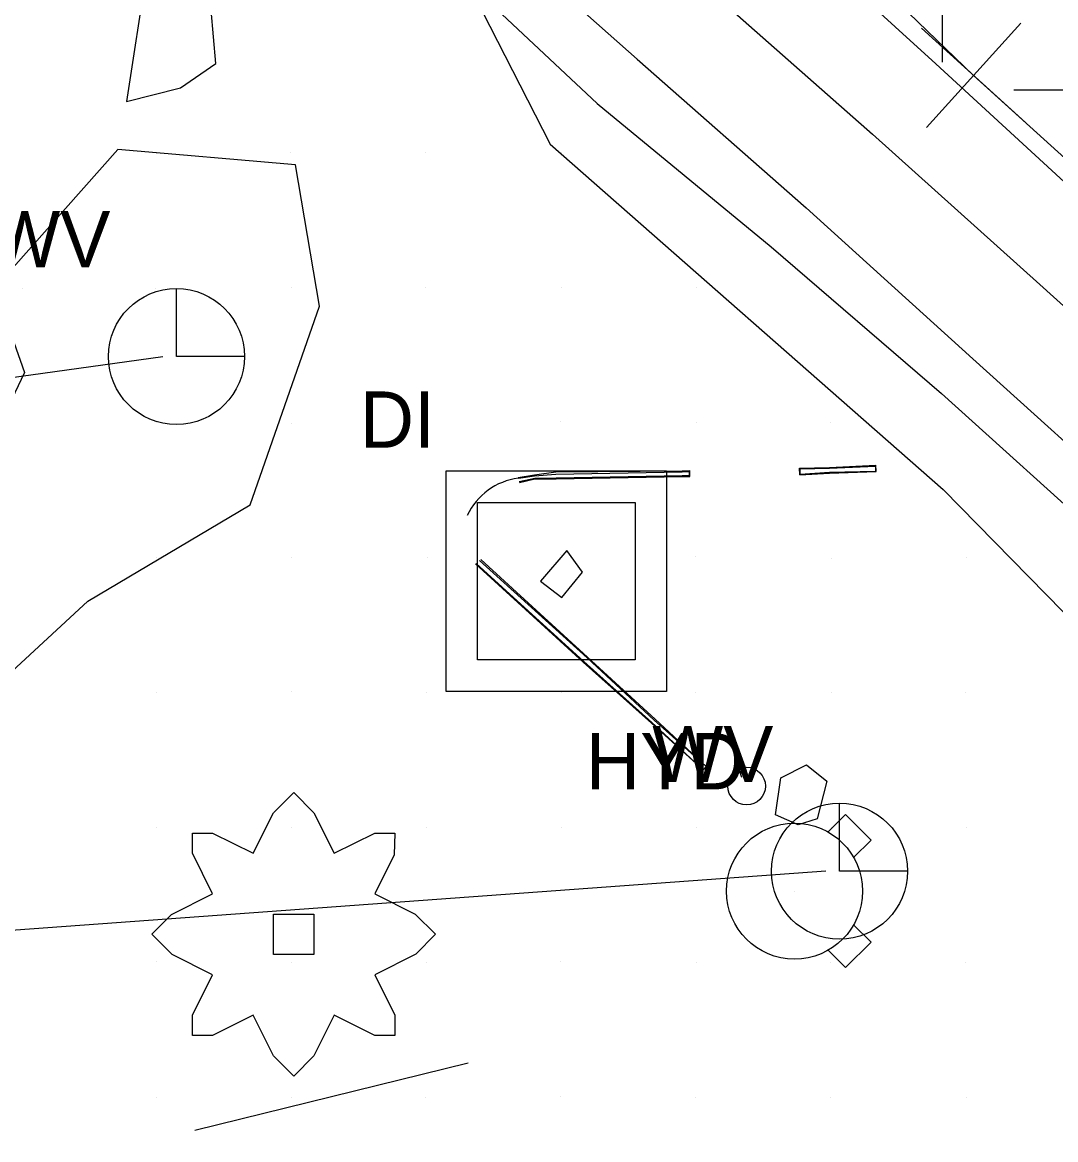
# Model space of a CAD drawing. Extents: x 1602514 to 1609837, y 863887 to 871157.
# Drawn here: x 1604998.8 to 1605113.6, y 866494.3 to 866618.4 of the extents above; entities that cross this region are included whole.
import ezdxf

# ---------------------------------------------------------------- set-up
doc = ezdxf.new("R2010")
doc.units = 0
for name, color, linetype in [('Default', 7, 'Continuous'), ('Drainage-Structures', 7, 'Continuous'), ('Environmental-New trees', 7, 'Continuous'), ('Survey-Centerline', 7, 'Continuous'), ('Survey-Drainage structures-concrete', 7, 'Continuous'), ('Survey-Edge of pavement', 7, 'Continuous'), ('Survey-Point', 7, 'Continuous'), ('Survey-Ridge Lines', 7, 'Continuous'), ('Survey-Shoulders', 7, 'Continuous'), ('Survey-Signs', 7, 'Continuous'), ('Survey-Spot dirt', 7, 'Continuous'), ('Survey-Vegetation trees', 7, 'Continuous'), ('Survey-Walls', 7, 'Continuous'), ('Text General Notes', 7, 'Continuous'), ('USER-Boulder', 7, 'Continuous'), ('USER-Manhole lid', 7, 'Continuous'), ('USER-RipRap', 7, 'Continuous'), ('Utility-Water', 7, 'Continuous')]:
    doc.layers.add(name, color=color, linetype=linetype)

msp = doc.modelspace()

# ---------------------------------------------------------------- linework, layer by layer
at = {"layer": 'Default'}
msp.add_lwpolyline([(1605152.49, 866568.76), (1605131.42, 866588.1), (1605104.45, 866612.51), (1605090, 866626.47), (1605088.69, 866628.71)], dxfattribs=at)
msp.add_lwpolyline([(1605152.49, 866568.76), (1605131.42, 866588.1), (1605104.45, 866612.51), (1605090, 866626.47), (1605088.69, 866628.71)], dxfattribs=at)
at = {"layer": 'Drainage-Structures'}
for p, q in [((1605045.84, 866568.56), (1605070.34, 866568.56)), ((1605045.84, 866544.06), (1605045.84, 866568.56)), ((1605045.84, 866568.56), (1605070.34, 866568.56)), ((1605045.84, 866544.06), (1605045.84, 866568.56)), ((1605070.34, 866568.56), (1605070.34, 866544.06)), ((1605070.34, 866568.56), (1605070.34, 866544.06)), ((1605049.34, 866565.06), (1605066.84, 866565.06)), ((1605049.34, 866547.56), (1605049.34, 866565.06)), ((1605049.34, 866565.06), (1605066.84, 866565.06)), ((1605049.34, 866547.56), (1605049.34, 866565.06)), ((1605066.84, 866565.06), (1605066.84, 866547.56)), ((1605066.84, 866565.06), (1605066.84, 866547.56)), ((1605066.84, 866547.56), (1605049.34, 866547.56)), ((1605066.84, 866547.56), (1605049.34, 866547.56)), ((1605070.34, 866544.06), (1605045.84, 866544.06)), ((1605070.34, 866544.06), (1605045.84, 866544.06))]:
    msp.add_line(p, q, dxfattribs=at)
at = {"layer": 'Environmental-New trees'}
for points in [[(1605017.65, 866505.83), (1605017.65, 866508.08), (1605019.9, 866512.58), (1605015.4, 866514.83), (1605013.15, 866517.08), (1605015.34, 866519.28), (1605019.9, 866521.58), (1605017.65, 866526.08), (1605017.65, 866528.33), (1605019.9, 866528.33), (1605024.4, 866526.08), (1605026.65, 866530.59), (1605028.91, 866532.84), (1605031.16, 866530.59), (1605033.41, 866526.08), (1605037.91, 866528.33), (1605040.16, 866528.33), (1605040.07, 866525.91), (1605037.91, 866521.58), (1605042.41, 866519.33), (1605044.66, 866517.08), (1605042.47, 866514.89), (1605037.91, 866512.58), (1605040.16, 866508.08), (1605040.16, 866505.83), (1605037.91, 866505.83), (1605033.41, 866508.08), (1605031.16, 866503.58), (1605028.91, 866501.33), (1605026.65, 866503.58), (1605024.4, 866508.08), (1605019.9, 866505.83)], [(1605017.65, 866505.83), (1605017.65, 866508.08), (1605019.9, 866512.58), (1605015.4, 866514.83), (1605013.15, 866517.08), (1605015.34, 866519.28), (1605019.9, 866521.58), (1605017.65, 866526.08), (1605017.65, 866528.33), (1605019.9, 866528.33), (1605024.4, 866526.08), (1605026.65, 866530.59), (1605028.91, 866532.84), (1605031.16, 866530.59), (1605033.41, 866526.08), (1605037.91, 866528.33), (1605040.16, 866528.33), (1605040.07, 866525.91), (1605037.91, 866521.58), (1605042.41, 866519.33), (1605044.66, 866517.08), (1605042.47, 866514.89), (1605037.91, 866512.58), (1605040.16, 866508.08), (1605040.16, 866505.83), (1605037.91, 866505.83), (1605033.41, 866508.08), (1605031.16, 866503.58), (1605028.91, 866501.33), (1605026.65, 866503.58), (1605024.4, 866508.08), (1605019.9, 866505.83)], [(1605026.65, 866519.33), (1605031.16, 866519.33), (1605031.16, 866514.83), (1605026.65, 866514.83)], [(1605026.65, 866519.33), (1605031.16, 866519.33), (1605031.16, 866514.83), (1605026.65, 866514.83)]]:
    msp.add_lwpolyline(points, close=True, dxfattribs=at)
at = {"layer": 'Survey-Centerline'}
msp.add_lwpolyline([(1605037.69, 866656.39), (1605055.94, 866639.3), (1605074.48, 866622.54), (1605093.22, 866605.99), (1605111.81, 866589.27), (1605130.38, 866572.54), (1605149.03, 866555.9), (1605167.54, 866539.1), (1605186.09, 866522.35), (1605204.45, 866505.38), (1605222.87, 866488.48), (1605241.24, 866471.52), (1605259.83, 866454.8), (1605278.24, 866437.88), (1605296.47, 866420.77), (1605314.1, 866402.9), (1605330.94, 866384.38), (1605346.83, 866365.09), (1605361.55, 866344.83), (1605375.5, 866323.96)], dxfattribs=at)
msp.add_lwpolyline([(1605037.69, 866656.39), (1605055.94, 866639.3), (1605074.48, 866622.54), (1605093.22, 866605.99), (1605111.81, 866589.27), (1605130.38, 866572.54), (1605149.03, 866555.9), (1605167.54, 866539.1), (1605186.09, 866522.35), (1605204.45, 866505.38), (1605222.87, 866488.48), (1605241.24, 866471.52), (1605259.83, 866454.8), (1605278.24, 866437.88), (1605296.47, 866420.77), (1605314.1, 866402.9), (1605330.94, 866384.38), (1605346.83, 866365.09), (1605361.55, 866344.83), (1605375.5, 866323.96)], dxfattribs=at)
at = {"layer": 'Survey-Drainage structures-concrete'}
msp.add_lwpolyline([(1605056.34, 866556.31), (1605058.69, 866554.51), (1605061.01, 866557.32), (1605059.24, 866559.71)], close=True, dxfattribs=at)
msp.add_lwpolyline([(1605056.34, 866556.31), (1605058.69, 866554.51), (1605061.01, 866557.32), (1605059.24, 866559.71)], close=True, dxfattribs=at)
at = {"layer": 'Survey-Edge of pavement'}
for points in [[(1605045, 866665.21), (1605063.24, 866647.41), (1605081.79, 866630.65), (1605100.27, 866613.81), (1605118.67, 866596.89), (1605137.24, 866580.16), (1605155.84, 866563.45), (1605174.61, 866546.94), (1605193.13, 866529.98), (1605211.59, 866513.11), (1605230.01, 866496.21), (1605248.38, 866479.26), (1605267.08, 866462.66), (1605285.49, 866445.74), (1605303.72, 866428.63), (1605322.49, 866409.74), (1605339.33, 866391.21), (1605355.22, 866371.92), (1605369.93, 866351.67), (1605383.89, 866330.79)], [(1605045, 866665.21), (1605063.24, 866647.41), (1605081.79, 866630.65), (1605100.27, 866613.81), (1605118.67, 866596.89), (1605137.24, 866580.16), (1605155.84, 866563.45), (1605174.61, 866546.94), (1605193.13, 866529.98), (1605211.59, 866513.11), (1605230.01, 866496.21), (1605248.38, 866479.26), (1605267.08, 866462.66), (1605285.49, 866445.74), (1605303.72, 866428.63), (1605322.49, 866409.74), (1605339.33, 866391.21), (1605355.22, 866371.92), (1605369.93, 866351.67), (1605383.89, 866330.79)], [(1605024.15, 866652.85), (1605048.37, 866630.9), (1605067.06, 866614.3), (1605085.84, 866597.8), (1605104.37, 866581.02), (1605122.94, 866564.29), (1605141.59, 866547.64), (1605160.11, 866530.85), (1605178.38, 866513.98), (1605196.73, 866497.01), (1605215.15, 866480.11), (1605233.53, 866463.16), (1605252.21, 866446.54), (1605270.61, 866429.62), (1605288.84, 866412.51), (1605305.39, 866395.8), (1605322.22, 866377.27), (1605338.18, 866358.03), (1605352.89, 866337.77)], [(1605024.15, 866652.85), (1605048.37, 866630.9), (1605067.06, 866614.3), (1605085.84, 866597.8), (1605104.37, 866581.02), (1605122.94, 866564.29), (1605141.59, 866547.64), (1605160.11, 866530.85), (1605178.38, 866513.98), (1605196.73, 866497.01), (1605215.15, 866480.11), (1605233.53, 866463.16), (1605252.21, 866446.54), (1605270.61, 866429.62), (1605288.84, 866412.51), (1605305.39, 866395.8), (1605322.22, 866377.27), (1605338.18, 866358.03), (1605352.89, 866337.77)]]:
    msp.add_lwpolyline(points, dxfattribs=at)
at = {"layer": 'Survey-Point'}
for p, q in [((1605098.66, 866617.76), (1605110.24, 866607.27)), ((1605099.21, 866606.72), (1605109.69, 866618.31))]:
    msp.add_line(p, q, dxfattribs=at)
at = {"layer": 'Survey-Ridge Lines'}
for points in [[(1605053.86, 866567.84), (1605055.65, 866568.12), (1605058.02, 866568.45), (1605072.06, 866568.59), (1605072.93, 866568.62)], [(1605053.86, 866567.84), (1605055.65, 866568.12), (1605058.02, 866568.45), (1605072.06, 866568.59), (1605072.93, 866568.62)], [(1605053.99, 866567.28), (1605055.71, 866567.69), (1605058.07, 866567.7), (1605072.08, 866567.95), (1605072.94, 866567.93), (1605072.93, 866568.62)], [(1605053.99, 866567.28), (1605055.71, 866567.69), (1605058.07, 866567.7), (1605072.08, 866567.95), (1605072.94, 866567.93), (1605072.93, 866568.62)], [(1605085.14, 866568.14), (1605085.12, 866568.86), (1605088.46, 866568.95), (1605093.61, 866569.19)], [(1605085.14, 866568.14), (1605085.12, 866568.86), (1605088.46, 866568.95), (1605093.61, 866569.19)], [(1605085.14, 866568.14), (1605088.46, 866568.31), (1605093.65, 866568.49), (1605093.61, 866569.19)], [(1605085.14, 866568.14), (1605088.46, 866568.31), (1605093.65, 866568.49), (1605093.61, 866569.19)], [(1605074.39, 866535.37), (1605068.65, 866540.53), (1605061.08, 866547.32), (1605049.12, 866558.25)], [(1605074.39, 866535.37), (1605068.65, 866540.53), (1605061.08, 866547.32), (1605049.12, 866558.25)], [(1605074.74, 866535.71), (1605069.06, 866541), (1605061.55, 866547.86), (1605049.72, 866558.72)], [(1605074.74, 866535.71), (1605069.06, 866541), (1605061.55, 866547.86), (1605049.72, 866558.72)]]:
    msp.add_lwpolyline(points, dxfattribs=at)
at = {"layer": 'Survey-Shoulders'}
for points in [[(1605020.8, 866649.24), (1605044.41, 866626.5), (1605062.62, 866609.38), (1605081.95, 866593.48), (1605100.89, 866577.16), (1605119.46, 866560.43), (1605138.12, 866543.79), (1605156.63, 866526.99), (1605174.63, 866509.92), (1605193.24, 866493.23), (1605211.66, 866476.33), (1605230.03, 866459.38), (1605248.15, 866442.14), (1605266.22, 866424.86), (1605284.45, 866407.75), (1605300.72, 866391.99), (1605317.55, 866373.46), (1605333.45, 866354.17), (1605347.38, 866333.28)], [(1605020.8, 866649.24), (1605044.41, 866626.5), (1605062.62, 866609.38), (1605081.95, 866593.48), (1605100.89, 866577.16), (1605119.46, 866560.43), (1605138.12, 866543.79), (1605156.63, 866526.99), (1605174.63, 866509.92), (1605193.24, 866493.23), (1605211.66, 866476.33), (1605230.03, 866459.38), (1605248.15, 866442.14), (1605266.22, 866424.86), (1605284.45, 866407.75), (1605300.72, 866391.99), (1605317.55, 866373.46), (1605333.45, 866354.17), (1605347.38, 866333.28)], [(1605048.2, 866622.94), (1605057.41, 866604.87), (1605101.07, 866566.51), (1605125.82, 866541.27), (1605141.44, 866528.64), (1605159.45, 866510.73), (1605192.41, 866483.04)], [(1605048.2, 866622.94), (1605057.41, 866604.87), (1605101.07, 866566.51), (1605125.82, 866541.27), (1605141.44, 866528.64), (1605159.45, 866510.73), (1605192.41, 866483.04)]]:
    msp.add_lwpolyline(points, dxfattribs=at)
at = {"layer": 'Survey-Signs'}
msp.add_line((1605017.93, 866495.32), (1605048.28, 866502.82), dxfattribs=at)
msp.add_line((1605017.93, 866495.32), (1605048.28, 866502.82), dxfattribs=at)
at = {"layer": 'Survey-Spot dirt'}
for p, q in [((1605100.96, 866629.6), (1605100.96, 866613.98)), ((1605124.56, 866610.89), (1605108.93, 866610.89)), ((1605013.63, 866603.79), (1605013.63, 866603.79)), ((1605013.63, 866603.79), (1605013.63, 866603.79)), ((1605028.58, 866603.96), (1605028.58, 866603.96)), ((1605028.58, 866603.96), (1605028.58, 866603.96)), ((1605043.55, 866603.92), (1605043.55, 866603.92)), ((1605043.55, 866603.92), (1605043.55, 866603.92)), ((1605058.62, 866603.98), (1605058.62, 866603.98)), ((1605058.62, 866603.98), (1605058.62, 866603.98)), ((1604998.78, 866588.79), (1604998.78, 866588.79)), ((1604998.78, 866588.79), (1604998.78, 866588.79)), ((1605013.55, 866588.89), (1605013.55, 866588.89)), ((1605013.55, 866588.89), (1605013.55, 866588.89)), ((1605028.63, 866588.98), (1605028.63, 866588.98)), ((1605028.63, 866588.98), (1605028.63, 866588.98)), ((1605043.58, 866588.96), (1605043.58, 866588.96)), ((1605043.58, 866588.96), (1605043.58, 866588.96)), ((1605058.65, 866588.97), (1605058.65, 866588.97)), ((1605058.65, 866588.97), (1605058.65, 866588.97)), ((1605073.66, 866588.99), (1605073.66, 866588.99)), ((1605073.66, 866588.99), (1605073.66, 866588.99)), ((1605013.61, 866573.95), (1605013.61, 866573.95)), ((1605013.61, 866573.95), (1605013.61, 866573.95)), ((1605028.66, 866573.86), (1605028.66, 866573.86)), ((1605028.66, 866573.86), (1605028.66, 866573.86)), ((1605043.62, 866574.02), (1605043.62, 866574.02)), ((1605043.62, 866574.02), (1605043.62, 866574.02)), ((1605058.53, 866574.01), (1605058.53, 866574.01)), ((1605058.53, 866574.01), (1605058.53, 866574.01)), ((1605073.64, 866573.99), (1605073.64, 866573.99)), ((1605073.64, 866573.99), (1605073.64, 866573.99)), ((1605088.58, 866573.97), (1605088.58, 866573.97)), ((1605088.58, 866573.97), (1605088.58, 866573.97)), ((1605013.62, 866558.95), (1605013.62, 866558.95)), ((1605013.62, 866558.95), (1605013.62, 866558.95)), ((1605028.61, 866558.99), (1605028.61, 866558.99)), ((1605028.61, 866558.99), (1605028.61, 866558.99)), ((1605043.75, 866558.91), (1605043.75, 866558.91)), ((1605043.75, 866558.91), (1605043.75, 866558.91)), ((1605058.55, 866559.3), (1605058.55, 866559.3)), ((1605058.55, 866559.3), (1605058.55, 866559.3)), ((1605073.55, 866559.01), (1605073.55, 866559.01)), ((1605073.55, 866559.01), (1605073.55, 866559.01)), ((1605088.66, 866558.87), (1605088.66, 866558.87)), ((1605088.66, 866558.87), (1605088.66, 866558.87)), ((1605103.64, 866558.92), (1605103.64, 866558.92)), ((1605103.64, 866558.92), (1605103.64, 866558.92)), ((1605013.64, 866543.92), (1605013.64, 866543.92)), ((1605013.64, 866543.92), (1605013.64, 866543.92)), ((1605028.65, 866544.02), (1605028.65, 866544.02)), ((1605028.65, 866544.02), (1605028.65, 866544.02)), ((1605043.61, 866543.98), (1605043.61, 866543.98)), ((1605043.61, 866543.98), (1605043.61, 866543.98)), ((1605058.65, 866543.91), (1605058.65, 866543.91)), ((1605058.65, 866543.91), (1605058.65, 866543.91)), ((1605073.6, 866543.99), (1605073.6, 866543.99)), ((1605073.6, 866543.99), (1605073.6, 866543.99)), ((1605088.68, 866543.99), (1605088.68, 866543.99)), ((1605088.68, 866543.99), (1605088.68, 866543.99)), ((1605103.59, 866543.98), (1605103.59, 866543.98)), ((1605103.59, 866543.98), (1605103.59, 866543.98)), ((1605013.66, 866528.94), (1605013.66, 866528.94)), ((1605013.66, 866528.94), (1605013.66, 866528.94)), ((1605028.67, 866529), (1605028.67, 866529)), ((1605028.67, 866529), (1605028.67, 866529)), ((1605043.68, 866528.9), (1605043.68, 866528.9)), ((1605043.68, 866528.9), (1605043.68, 866528.9)), ((1605058.66, 866528.96), (1605058.66, 866528.96)), ((1605058.66, 866528.96), (1605058.66, 866528.96)), ((1605073.66, 866528.97), (1605073.66, 866528.97)), ((1605073.66, 866528.97), (1605073.66, 866528.97)), ((1605088.63, 866528.98), (1605088.63, 866528.98)), ((1605088.63, 866528.98), (1605088.63, 866528.98)), ((1605103.65, 866528.97), (1605103.65, 866528.97)), ((1605103.65, 866528.97), (1605103.65, 866528.97)), ((1605013.7, 866514.01), (1605013.7, 866514.01)), ((1605013.7, 866514.01), (1605013.7, 866514.01)), ((1605028.64, 866513.92), (1605028.64, 866513.92)), ((1605028.64, 866513.92), (1605028.64, 866513.92)), ((1605043.64, 866513.94), (1605043.64, 866513.94)), ((1605043.64, 866513.94), (1605043.64, 866513.94)), ((1605058.6, 866514.08), (1605058.6, 866514.08)), ((1605058.6, 866514.08), (1605058.6, 866514.08)), ((1605073.63, 866513.96), (1605073.63, 866513.96)), ((1605073.63, 866513.96), (1605073.63, 866513.96)), ((1605088.58, 866513.97), (1605088.58, 866513.97)), ((1605088.58, 866513.97), (1605088.58, 866513.97)), ((1605103.55, 866513.99), (1605103.55, 866513.99)), ((1605103.55, 866513.99), (1605103.55, 866513.99)), ((1605013.63, 866498.99), (1605013.63, 866498.99)), ((1605013.63, 866498.99), (1605013.63, 866498.99)), ((1605028.63, 866498.91), (1605028.63, 866498.91)), ((1605028.63, 866498.91), (1605028.63, 866498.91)), ((1605043.59, 866498.96), (1605043.59, 866498.96)), ((1605043.59, 866498.96), (1605043.59, 866498.96)), ((1605058.59, 866499.02), (1605058.59, 866499.02)), ((1605058.59, 866499.02), (1605058.59, 866499.02)), ((1605073.61, 866498.95), (1605073.61, 866498.95)), ((1605073.61, 866498.95), (1605073.61, 866498.95)), ((1605088.58, 866498.98), (1605088.58, 866498.98)), ((1605088.58, 866498.98), (1605088.58, 866498.98)), ((1605103.62, 866498.97), (1605103.62, 866498.97)), ((1605103.62, 866498.97), (1605103.62, 866498.97))]:
    msp.add_line(p, q, dxfattribs=at)
at = {"layer": 'Survey-Vegetation trees'}
msp.add_lwpolyline([(1604901.74, 866478.85), (1604927.14, 866484.54), (1604943.52, 866501.59), (1604946.2, 866513.63), (1604958.56, 866523.67), (1604973.27, 866521.99), (1604988.65, 866538.05), (1605006.03, 866554.1), (1605024.08, 866564.8), (1605031.76, 866586.88), (1605029.09, 866602.59), (1605009.37, 866604.27), (1604995.66, 866588.88), (1604999.01, 866579.52), (1604995, 866571.16), (1604985.3, 866563.8), (1604976.28, 866564.47), (1604958.9, 866541.06), (1604954.89, 866528.35), (1604938.17, 866513.97), (1604928.15, 866511.29), (1604908.43, 866495.91), (1604898.59, 866490.95)], dxfattribs=at)
msp.add_lwpolyline([(1604901.74, 866478.85), (1604927.14, 866484.54), (1604943.52, 866501.59), (1604946.2, 866513.63), (1604958.56, 866523.67), (1604973.27, 866521.99), (1604988.65, 866538.05), (1605006.03, 866554.1), (1605024.08, 866564.8), (1605031.76, 866586.88), (1605029.09, 866602.59), (1605009.37, 866604.27), (1604995.66, 866588.88), (1604999.01, 866579.52), (1604995, 866571.16), (1604985.3, 866563.8), (1604976.28, 866564.47), (1604958.9, 866541.06), (1604954.89, 866528.35), (1604938.17, 866513.97), (1604928.15, 866511.29), (1604908.43, 866495.91), (1604898.59, 866490.95)], dxfattribs=at)
at = {"layer": 'Survey-Walls'}
for points in [[(1605053.88, 866567.76), (1605055.67, 866568.04), (1605058.04, 866568.21), (1605072.06, 866568.46), (1605072.85, 866568.52), (1605072.85, 866568.07)], [(1605053.88, 866567.76), (1605055.67, 866568.04), (1605058.04, 866568.21), (1605072.06, 866568.46), (1605072.85, 866568.52), (1605072.85, 866568.07)], [(1605053.97, 866567.38), (1605055.7, 866567.78), (1605058.06, 866567.8), (1605072.08, 866568.07), (1605072.85, 866568.07)], [(1605053.97, 866567.38), (1605055.7, 866567.78), (1605058.06, 866567.8), (1605072.08, 866568.07), (1605072.85, 866568.07)], [(1605085.17, 866568.21), (1605085.19, 866568.81), (1605088.46, 866568.88), (1605093.56, 866569.08), (1605093.56, 866568.55)], [(1605085.17, 866568.21), (1605085.19, 866568.81), (1605088.46, 866568.88), (1605093.56, 866569.08), (1605093.56, 866568.55)], [(1605085.17, 866568.21), (1605088.46, 866568.44), (1605093.56, 866568.55)], [(1605085.17, 866568.21), (1605088.46, 866568.44), (1605093.56, 866568.55)], [(1605049.17, 866558.29), (1605061.15, 866547.4), (1605068.7, 866540.6), (1605074.39, 866535.37), (1605074.74, 866535.71), (1605068.95, 866540.87), (1605061.5, 866547.8), (1605049.57, 866558.6)], [(1605049.17, 866558.29), (1605061.15, 866547.4), (1605068.7, 866540.6), (1605074.39, 866535.37), (1605074.74, 866535.71), (1605068.95, 866540.87), (1605061.5, 866547.8), (1605049.57, 866558.6)]]:
    msp.add_lwpolyline(points, dxfattribs=at)
msp.add_arc((1605054.81, 866560.5), 7.32, 97.2649, 154.8071, dxfattribs=at)
msp.add_arc((1605054.81, 866560.5), 7.32, 97.2649, 154.8071, dxfattribs=at)
at = {"layer": 'Text General Notes'}
msp.add_line((1605088.05, 866524.09), (1604065.19, 866449.51), dxfattribs=at)
msp.add_line((1605088.05, 866524.09), (1604065.19, 866449.51), dxfattribs=at)
msp.add_lwpolyline([(1605012.85, 866633.37), (1604065.19, 866449.51), (1605014.37, 866581.28)], dxfattribs=at)
msp.add_lwpolyline([(1605012.85, 866633.37), (1604065.19, 866449.51), (1605014.37, 866581.28)], dxfattribs=at)
at = {"layer": 'USER-Boulder'}
msp.add_lwpolyline([(1605084.95, 866529.23), (1605082.45, 866530.37), (1605083.05, 866534.47), (1605085.9, 866535.9), (1605088.16, 866534.08), (1605087.08, 866529.93), (1605084.95, 866529.23)], dxfattribs=at)
msp.add_lwpolyline([(1605084.95, 866529.23), (1605082.45, 866530.37), (1605083.05, 866534.47), (1605085.9, 866535.9), (1605088.16, 866534.08), (1605087.08, 866529.93), (1605084.95, 866529.23)], dxfattribs=at)
at = {"layer": 'USER-Manhole lid'}
for p, q in [((1605078.71, 866534.51), (1605078.46, 866535.24)), ((1605078.46, 866535.24), (1605078.81, 866534.83)), ((1605078.71, 866534.51), (1605078.46, 866535.24)), ((1605078.46, 866535.24), (1605078.81, 866534.83)), ((1605078.81, 866534.83), (1605078.83, 866535.37)), ((1605078.81, 866534.83), (1605078.83, 866535.37)), ((1605078.83, 866535.37), (1605079.08, 866534.64)), ((1605078.83, 866535.37), (1605079.08, 866534.64)), ((1605079.46, 866534.65), (1605079.69, 866535.38)), ((1605079.46, 866534.65), (1605079.69, 866535.38)), ((1605079.95, 866534.92), (1605079.58, 866535.03)), ((1605079.95, 866534.92), (1605079.58, 866535.03)), ((1605079.83, 866534.54), (1605080.06, 866535.27)), ((1605079.83, 866534.54), (1605080.06, 866535.27))]:
    msp.add_line(p, q, dxfattribs=at)
msp.add_circle((1605079.24, 866533.55), 2.09, dxfattribs=at)
msp.add_circle((1605079.24, 866533.55), 2.09, dxfattribs=at)
at = {"layer": 'USER-RipRap'}
msp.add_lwpolyline([(1605012.76, 866637.08), (1605012.59, 866624.32), (1605010.33, 866609.61), (1605016.31, 866611.12), (1605020.27, 866613.85), (1605019.22, 866625.72), (1605018.06, 866637.18), (1605012.76, 866637.08)], dxfattribs=at)
msp.add_lwpolyline([(1605012.76, 866637.08), (1605012.59, 866624.32), (1605010.33, 866609.61), (1605016.31, 866611.12), (1605020.27, 866613.85), (1605019.22, 866625.72), (1605018.06, 866637.18), (1605012.76, 866637.08)], dxfattribs=at)
at = {"layer": 'Utility-Water'}
for p, q in [((1605015.88, 866581.28), (1605015.88, 866588.84)), ((1605015.88, 866581.28), (1605015.88, 866588.84)), ((1605015.88, 866581.28), (1605015.88, 866581.28)), ((1605023.44, 866581.28), (1605015.88, 866581.28)), ((1605015.88, 866581.28), (1605015.88, 866581.28)), ((1605023.44, 866581.28), (1605015.88, 866581.28)), ((1605089.56, 866524.09), (1605089.56, 866531.65)), ((1605089.56, 866524.09), (1605089.56, 866531.65)), ((1605088.3, 866528.45), (1605090.23, 866530.39)), ((1605088.3, 866528.45), (1605090.23, 866530.39)), ((1605090.23, 866530.39), (1605093.07, 866527.55)), ((1605090.23, 866530.39), (1605093.07, 866527.55)), ((1605093.07, 866527.55), (1605091.13, 866525.62)), ((1605093.07, 866527.55), (1605091.13, 866525.62)), ((1605089.56, 866524.09), (1605089.56, 866524.09)), ((1605097.12, 866524.09), (1605089.56, 866524.09)), ((1605089.56, 866524.09), (1605089.56, 866524.09)), ((1605097.12, 866524.09), (1605089.56, 866524.09)), ((1605084.56, 866521.88), (1605084.56, 866521.88)), ((1605084.56, 866521.88), (1605084.56, 866521.88)), ((1605091.13, 866518.13), (1605093.07, 866516.21)), ((1605091.13, 866518.13), (1605093.07, 866516.21)), ((1605093.07, 866516.21), (1605090.23, 866513.38)), ((1605093.07, 866516.21), (1605090.23, 866513.38)), ((1605090.23, 866513.38), (1605088.3, 866515.31)), ((1605090.23, 866513.38), (1605088.3, 866515.31))]:
    msp.add_line(p, q, dxfattribs=at)
for centre in [(1605015.88, 866581.28), (1605015.88, 866581.28), (1605089.56, 866524.09), (1605089.56, 866524.09), (1605084.56, 866521.88), (1605084.56, 866521.88)]:
    msp.add_circle(centre, 7.56, dxfattribs=at)

# ---------------------------------------------------------------- texts
at = {"layer": 'Drainage-Structures'}
msp.add_text('DI', height=6.25, dxfattribs=at).set_placement((1605036.24, 866571.15))
msp.add_text('DI', height=6.25, dxfattribs=at).set_placement((1605036.24, 866571.15))
at = {"layer": 'Utility-Water'}
for s, p in [('WV', (1604995.07, 866591.18)), ('WV', (1604995.07, 866591.18)), ('WV', (1605068.75, 866533.99)), ('WV', (1605068.75, 866533.99)), ('HYD', (1605061.38, 866533.19)), ('HYD', (1605061.38, 866533.19))]:
    msp.add_text(s, height=6.251, dxfattribs=at).set_placement(p)

doc.saveas('drawing.dxf')
